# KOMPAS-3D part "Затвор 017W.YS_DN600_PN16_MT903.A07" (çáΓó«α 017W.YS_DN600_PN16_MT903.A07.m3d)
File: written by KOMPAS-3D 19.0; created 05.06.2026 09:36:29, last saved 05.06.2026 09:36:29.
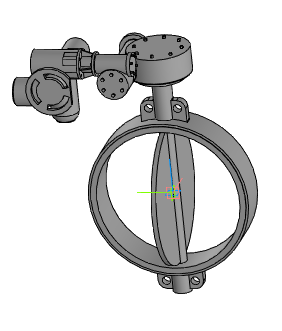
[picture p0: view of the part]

Document properties: Автор: Энергия; Полное имя файла: ..\..\..\3d для проектировщиков\x.x Тип 017W.Y(S) Затвор дисковый поворотный межфланцевый\Затвор 017W.Y(S)_DN32-DN1200_QT.A_MT903.A\Затвор 017W.YS_DN600_PN16_MT903.A07.a3d

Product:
- Part/product: Затвор 017W.YS_DN600_PN16_MT903.A07
    Масса: 298.788

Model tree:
1. Операция без истории:1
